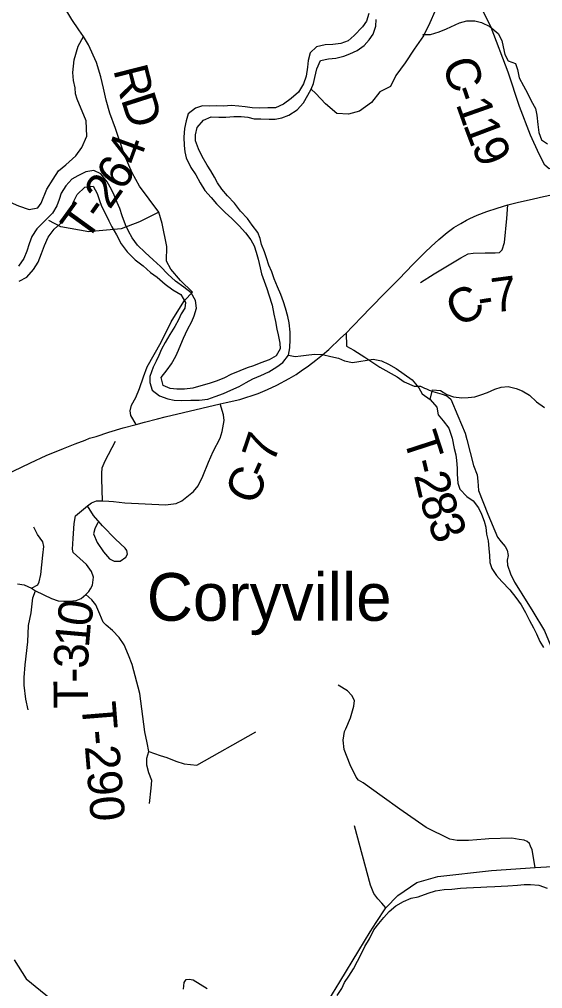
# Model space of a CAD drawing. Extents: x 0 to 34, y 0 to 22.
# Drawn here: x 3.344 to 4.209, y 15.794 to 17.398 of the extents above; entities that cross this region are included whole.
import ezdxf

# ---------------------------------------------------------------- set-up
doc = ezdxf.new("R2010")
doc.units = 0
for name, color, linetype in [('GM_X_City_Street', 7, 'Continuous'), ('GM_X_County_Road', 7, 'Continuous'), ('GM_X_County_Road_Text', 7, 'Continuous'), ('GM_X_Major_River', 7, 'Continuous'), ('GM_X_Minor_River', 7, 'Continuous'), ('GM_X_State_Route', 7, 'Continuous'), ('GM_X_Township_Road', 7, 'Continuous'), ('GM_X_Township_Road_Text', 7, 'Continuous'), ('GM_X_Unincorporated_Text', 7, 'Continuous')]:
    doc.layers.add(name, color=color, linetype=linetype)

msp = doc.modelspace()

# ---------------------------------------------------------------- linework, layer by layer
at = {"layer": 'GM_X_City_Street'}
for points in [[(3.3351, 15.8422), (3.355, 15.8107), (3.4028, 15.7721)], [(3.6151, 15.7933), (3.6163, 15.8047), (3.6197, 15.8093), (3.6246, 15.81), (3.6311, 15.8088), (3.6545, 15.7947)]]:
    msp.add_lwpolyline(points, dxfattribs=at)
at = {"layer": 'GM_X_County_Road'}
for points in [[(3.5371, 16.7279), (3.5284, 16.7427), (3.5273, 16.7507), (3.5295, 16.7598), (3.5364, 16.7725), (3.5425, 16.7873), (3.5494, 16.8066), (3.555, 16.8235), (3.5785, 16.8642), (3.595, 16.8979), (3.6074, 16.9184), (3.6169, 16.9333), (3.6305, 16.9469), (3.6106, 16.9661), (3.5945, 16.9852), (3.5873, 16.9983), (3.5879, 17.0227), (3.5802, 17.0607), (3.5744, 17.0795), (3.5427, 17.1224), (3.5305, 17.1447), (3.5177, 17.174), (3.503, 17.2177), (3.4935, 17.2431), (3.4877, 17.2645), (3.483, 17.2848), (3.4786, 17.3036), (3.4713, 17.3273), (3.4585, 17.3566), (3.4498, 17.3701), (3.4422, 17.3814), (3.4305, 17.3981), (3.419, 17.4174)], [(4.2627, 17.1168), (4.257, 17.1291), (4.2524, 17.1378), (4.2427, 17.15), (4.2346, 17.1567), (4.2201, 17.1513), (4.2127, 17.1571), (4.2036, 17.1755), (4.1895, 17.207), (4.1712, 17.2541), (4.1524, 17.3111), (4.1244, 17.385), (4.1095, 17.4154)], [(4.1518, 17.0918), (4.1671, 17.0954), (4.194, 17.1014), (4.211, 17.1054), (4.2342, 17.1105), (4.2627, 17.1168)], [(4.0072, 16.9628), (4.0299, 16.9772), (4.0741, 17.0039), (4.086, 17.0102), (4.0943, 17.0115), (4.1141, 17.0122), (4.1307, 17.0119), (4.1379, 17.0128), (4.1422, 17.0173), (4.1462, 17.029), (4.1501, 17.0688), (4.1518, 17.0918)], [(3.3411, 16.4643), (3.3518, 16.4626), (3.3642, 16.4572), (3.3704, 16.4526), (3.3973, 16.4398), (3.4079, 16.4359), (3.4172, 16.4356), (3.4268, 16.4356), (3.4377, 16.4366), (3.4463, 16.4401), (3.454, 16.4468), (3.4588, 16.4518), (3.4614, 16.4561), (3.4649, 16.4622), (3.4667, 16.4752), (3.4633, 16.4848), (3.455, 16.4965), (3.4327, 16.5162), (3.4316, 16.5216), (3.4329, 16.5391), (3.4345, 16.5642), (3.437, 16.5767), (3.4566, 16.5935), (3.4631, 16.5981), (3.4715, 16.6017), (3.4813, 16.6017), (3.4921, 16.6013), (3.4994, 16.6006), (3.5186, 16.5981), (3.5856, 16.5952), (3.6034, 16.597), (3.6128, 16.6014), (3.6317, 16.6169), (3.6396, 16.6267), (3.6476, 16.6423), (3.6567, 16.6655), (3.6643, 16.6833), (3.6762, 16.7054), (3.6795, 16.7163), (3.6824, 16.7348), (3.6813, 16.7438), (3.6762, 16.762)], [(3.4813, 16.6017), (3.4802, 16.6383), (3.4805, 16.647), (3.4809, 16.6561), (3.4856, 16.6677), (3.503, 16.7003)]]:
    msp.add_lwpolyline(points, dxfattribs=at)
at = {"layer": 'GM_X_Major_River'}
for points in [[(3.922, 17.408), (3.9182, 17.3955), (3.9114, 17.386), (3.8978, 17.3716), (3.8876, 17.3632), (3.8755, 17.3587), (3.8626, 17.3571), (3.8498, 17.3564), (3.8354, 17.3533), (3.8248, 17.3431), (3.8218, 17.3302), (3.8203, 17.3192), (3.8184, 17.3047), (3.8138, 17.2918), (3.8055, 17.2778), (3.7934, 17.2675), (3.781, 17.2584), (3.7677, 17.252), (3.7549, 17.2523), (3.7416, 17.2516), (3.7292, 17.2523), (3.7171, 17.2538), (3.7069, 17.255), (3.694, 17.2557), (3.6819, 17.255), (3.6698, 17.2553), (3.6577, 17.2546), (3.6468, 17.2553), (3.635, 17.2515), (3.6233, 17.242), (3.6195, 17.2303), (3.6169, 17.2181), (3.6158, 17.2037), (3.6165, 17.1897), (3.6173, 17.179), (3.6195, 17.1692), (3.6275, 17.1536), (3.6358, 17.1411), (3.643, 17.1282), (3.6509, 17.1153), (3.6611, 17.1036), (3.6698, 17.0933), (3.6845, 17.0789), (3.6955, 17.069), (3.7076, 17.0569), (3.7178, 17.0451), (3.7265, 17.0334), (3.7321, 17.0235), (3.7356, 17.0133), (3.739, 17.0015), (3.7423, 16.9871), (3.7442, 16.9776), (3.7488, 16.9651), (3.7533, 16.953), (3.7567, 16.9427), (3.762, 16.9253), (3.765, 16.9108), (3.7673, 16.8983), (3.7699, 16.8858), (3.7722, 16.8763), (3.7748, 16.8627), (3.7752, 16.8532), (3.7688, 16.8414), (3.7571, 16.835), (3.7435, 16.83), (3.731, 16.8251)], [(3.7189, 16.7974), (3.7298, 16.8035), (3.7435, 16.8088), (3.7567, 16.8152), (3.7699, 16.8236), (3.7797, 16.8308), (3.7888, 16.8429), (3.7911, 16.8551), (3.7915, 16.8684), (3.7919, 16.8809), (3.7903, 16.8964), (3.7881, 16.9067), (3.7843, 16.9203), (3.7805, 16.931), (3.7764, 16.9431), (3.7707, 16.956), (3.7654, 16.9689), (3.7616, 16.9807), (3.7567, 16.9917), (3.7526, 17.0038), (3.7492, 17.014), (3.7446, 17.0258), (3.742, 17.0357), (3.7382, 17.0455), (3.7291, 17.058), (3.7212, 17.0687), (3.7095, 17.0812), (3.6997, 17.0945), (3.6883, 17.1062), (3.6789, 17.1172), (3.6717, 17.1278), (3.6664, 17.1373), (3.6603, 17.1479), (3.6547, 17.1574), (3.646, 17.1715), (3.6399, 17.184), (3.6354, 17.1977), (3.635, 17.2075), (3.6377, 17.2197), (3.6486, 17.2318), (3.6611, 17.2371), (3.6736, 17.2364), (3.6853, 17.2364), (3.6985, 17.2379), (3.711, 17.2379), (3.722, 17.2364), (3.7322, 17.2341), (3.7435, 17.2337), (3.7571, 17.2334), (3.767, 17.2334), (3.7779, 17.2353), (3.7893, 17.2398), (3.8033, 17.249), (3.8138, 17.2603), (3.821, 17.2729), (3.8263, 17.2827), (3.8301, 17.2926), (3.8327, 17.3025), (3.8358, 17.3165), (3.8422, 17.3306), (3.8551, 17.3332), (3.8675, 17.3344), (3.8808, 17.3374), (3.8906, 17.3416), (3.9027, 17.3469), (3.9144, 17.3553), (3.9227, 17.3648), (3.9292, 17.3742), (3.9337, 17.3872), (3.9341, 17.3985)], [(3.731, 16.8251), (3.7204, 16.8217), (3.7083, 16.8167), (3.6939, 16.8107), (3.683, 16.8053), (3.6713, 16.8004), (3.658, 16.7958), (3.644, 16.7917), (3.6308, 16.7879), (3.6172, 16.7867), (3.6043, 16.7867), (3.5934, 16.7878), (3.5817, 16.7924), (3.5786, 16.8057), (3.5885, 16.8186), (3.5953, 16.8284), (3.6025, 16.841), (3.607, 16.8508), (3.6112, 16.8603), (3.6153, 16.8709), (3.6221, 16.885), (3.6293, 16.8983), (3.6331, 16.9078), (3.6369, 16.9203), (3.635, 16.9332), (3.6282, 16.9461), (3.6157, 16.9552), (3.6021, 16.9654), (3.5896, 16.9768), (3.5772, 16.9893), (3.5654, 17.0003), (3.5522, 17.0124), (3.5394, 17.025), (3.5303, 17.0371), (3.5242, 17.0481), (3.5197, 17.0583), (3.514, 17.0731), (3.5099, 17.0857), (3.5054, 17.0955), (3.5008, 17.1073), (3.4963, 17.1171), (3.4891, 17.1297), (3.4789, 17.1426), (3.4668, 17.1482), (3.4536, 17.146), (3.4407, 17.1395), (3.4309, 17.1338), (3.4207, 17.1232), (3.4131, 17.1107), (3.4097, 17.1004), (3.4059, 17.0898), (3.3988, 17.0776), (3.373, 17.0518), (3.3643, 17.0389), (3.3602, 17.0268), (3.3564, 17.015), (3.3511, 17.0025), (3.3424, 16.9903)], [(3.3435, 16.9653), (3.356, 16.9718), (3.3674, 16.9843), (3.3749, 16.9968), (3.3806, 17.0108), (3.3855, 17.0241), (3.3916, 17.0382), (3.4014, 17.0511), (3.412, 17.0606), (3.4233, 17.0731), (3.4301, 17.086), (3.4328, 17.0955), (3.4396, 17.1084), (3.4521, 17.1205), (3.4657, 17.1224), (3.4725, 17.1103), (3.4766, 17.0989), (3.48, 17.0891), (3.4861, 17.0765), (3.4917, 17.0652), (3.497, 17.0549), (3.5046, 17.042), (3.5125, 17.0272), (3.522, 17.0139), (3.5356, 17.0003), (3.5484, 16.9908), (3.5609, 16.9794), (3.5719, 16.9718), (3.5851, 16.9605), (3.5979, 16.951), (3.6112, 16.9434), (3.6187, 16.9301), (3.6176, 16.9206), (3.6115, 16.9112), (3.607, 16.9013), (3.601, 16.8899), (3.593, 16.877), (3.5851, 16.8637), (3.579, 16.8527), (3.5745, 16.8421), (3.5703, 16.8326), (3.565, 16.8227), (3.5597, 16.8072), (3.5597, 16.7977), (3.5635, 16.7848), (3.5756, 16.7753), (3.5896, 16.7704), (3.6002, 16.7685), (3.6127, 16.7678), (3.6274, 16.7681), (3.6414, 16.7685), (3.6554, 16.77), (3.6678, 16.7742), (3.6815, 16.7792), (3.6939, 16.7849), (3.7072, 16.7909), (3.7189, 16.7974)]]:
    msp.add_lwpolyline(points, dxfattribs=at)
at = {"layer": 'GM_X_Minor_River'}
for points in [[(4.0992, 17.5016), (4.0829, 17.4803), (4.0753, 17.4632), (4.0612, 17.4453), (4.0487, 17.4282), (4.0309, 17.4114), (4.0225, 17.3928), (4.0122, 17.3715), (3.9967, 17.3494), (3.9822, 17.3266), (3.9667, 17.3057), (3.9575, 17.2875), (3.9401, 17.2783), (3.9261, 17.2609), (3.9067, 17.2464), (3.8885, 17.2415), (3.8689, 17.2427), (3.85, 17.2587), (3.8341, 17.2758), (3.8263, 17.2827)], [(4.0122, 17.3715), (4.0116, 17.3735), (4.0237, 17.3735), (4.0384, 17.3781), (4.0501, 17.3827), (4.072, 17.3925), (4.0838, 17.3963), (4.097, 17.3963), (4.108, 17.3933), (4.1219, 17.3865), (4.1355, 17.3751), (4.1416, 17.3633), (4.1439, 17.3531), (4.1469, 17.3402), (4.1525, 17.3299), (4.1643, 17.3254), (4.168, 17.3155), (4.1703, 17.3019), (4.1779, 17.2886), (4.1843, 17.2764), (4.1903, 17.2639), (4.1975, 17.251), (4.1998, 17.24), (4.2013, 17.2244), (4.2028, 17.2112), (4.2073, 17.199), (4.2172, 17.1926)], [(3.7888, 16.8429), (3.7998, 16.8407), (3.8096, 16.8418), (3.8228, 16.8433), (3.8327, 16.8445), (3.8455, 16.8441), (3.8588, 16.8403), (3.8716, 16.8377), (3.8814, 16.8335), (3.8947, 16.8308), (3.9056, 16.8324), (3.9189, 16.8346), (3.9291, 16.8362), (3.9427, 16.8335), (3.9544, 16.8278), (3.9669, 16.8206), (3.9805, 16.8111), (3.9933, 16.802), (4.0043, 16.7884), (4.0099, 16.7789), (4.0232, 16.7691), (4.0341, 16.7569), (4.0368, 16.744), (4.0447, 16.7338), (4.0542, 16.722), (4.0598, 16.7053), (4.0632, 16.6883), (4.0655, 16.678), (4.0666, 16.6682), (4.0678, 16.6556), (4.0681, 16.6458), (4.0689, 16.6306), (4.0723, 16.6208), (4.084, 16.6086), (4.0946, 16.6014), (4.1033, 16.59), (4.1082, 16.5794), (4.1127, 16.568), (4.1154, 16.5578), (4.1165, 16.5464), (4.1191, 16.5354), (4.1206, 16.5225), (4.1214, 16.5112), (4.1222, 16.4994), (4.1252, 16.4895), (4.1331, 16.4778), (4.1418, 16.4679), (4.155, 16.4543), (4.1652, 16.4414), (4.1736, 16.4296), (4.1807, 16.4167), (4.1875, 16.4035), (4.194, 16.3917), (4.1992, 16.3815), (4.2049, 16.3686), (4.2106, 16.3591)], [(3.7888, 16.8429), (3.7888, 16.8433)], [(4.0232, 16.7691), (4.0273, 16.7854), (4.0402, 16.7842), (4.0511, 16.7774), (4.0621, 16.774), (4.0757, 16.7721), (4.0859, 16.7725), (4.0973, 16.774), (4.1071, 16.7771), (4.1184, 16.7812), (4.1301, 16.7866), (4.1407, 16.7896), (4.1521, 16.7907), (4.1657, 16.7873), (4.1755, 16.7835), (4.1876, 16.7763), (4.1993, 16.7653), (4.2122, 16.7562)], [(3.8695, 15.7829), (3.8774, 15.7946), (3.8816, 15.8045), (3.8888, 15.8147), (3.8967, 15.8269), (3.9032, 15.8398), (3.9096, 15.8523), (3.9153, 15.8641), (3.9232, 15.8766), (3.93, 15.8914), (3.9383, 15.902), (3.9466, 15.9122), (3.9553, 15.9217), (3.9663, 15.9316), (3.9792, 15.9384), (3.992, 15.9441), (4.0034, 15.9464), (4.02, 15.9525), (4.0321, 15.9563), (4.0464, 15.9582), (4.0589, 15.9589), (4.0737, 15.9604), (4.0835, 15.9612), (4.0952, 15.9616), (4.1069, 15.9624), (4.1168, 15.9627), (4.13, 15.9635), (4.1406, 15.9639), (4.1519, 15.9647), (4.1678, 15.9658), (4.1787, 15.9669), (4.1893, 15.9669), (4.2029, 15.9654), (4.2169, 15.9605)]]:
    msp.add_lwpolyline(points, dxfattribs=at)
at = {"layer": 'GM_X_State_Route'}
for p, q in [((3.6762, 16.762), (3.686, 16.7643)), ((3.9342, 15.9036), (3.9501, 15.9279))]:
    msp.add_line(p, q, dxfattribs=at)
for points in [[(4.1518, 17.0918), (4.1671, 17.0954), (4.194, 17.1014), (4.211, 17.1054), (4.2342, 17.1105), (4.2627, 17.1168)], [(3.686, 16.7643), (3.7085, 16.7696), (3.7386, 16.7794), (3.7542, 16.7858), (3.7698, 16.7933), (3.7899, 16.8041), (3.8016, 16.811), (3.81, 16.8166), (3.8221, 16.8249), (3.8343, 16.8342), (3.8455, 16.8431), (3.8557, 16.852), (3.875, 16.8707), (3.8843, 16.8792), (3.8949, 16.8904), (3.9118, 16.9078), (3.923, 16.9193), (3.9507, 16.9477), (3.9719, 16.9693), (3.9948, 16.9927), (4.0029, 17.0011), (4.0148, 17.0131), (4.0247, 17.0226), (4.0378, 17.0344), (4.0517, 17.0456), (4.0625, 17.0538), (4.0738, 17.0608), (4.0834, 17.0661), (4.089, 17.0689), (4.1011, 17.0743), (4.117, 17.0807), (4.1341, 17.0862), (4.1518, 17.0918)], [(3.5371, 16.7279), (3.5508, 16.7321), (3.5726, 16.7373), (3.5853, 16.7406), (3.6762, 16.762)], [(3.102, 16.494), (3.1088, 16.5002), (3.1391, 16.5253), (3.158, 16.5407), (3.1695, 16.5496), (3.2033, 16.5739), (3.224, 16.5878), (3.2682, 16.6153), (3.2999, 16.6333), (3.3345, 16.6514), (3.3611, 16.6641), (3.3624, 16.6646), (3.3885, 16.6767), (3.4167, 16.6883), (3.4364, 16.6961), (3.4525, 16.702), (3.4601, 16.7051), (3.4709, 16.7083), (3.4917, 16.7154), (3.5156, 16.7225), (3.5371, 16.7279)], [(3.9501, 15.9279), (3.9698, 15.9484), (4.0012, 15.9699), (4.0362, 15.9799), (4.1249, 15.9899), (4.1968, 15.9947), (4.2431, 15.9978)], [(3.6204, 15.4648), (3.622, 15.466), (3.6381, 15.4802), (3.6679, 15.519), (3.681, 15.5402), (3.6917, 15.5618), (3.7094, 15.6057), (3.7367, 15.6553), (3.7625, 15.6833), (3.8051, 15.7156), (3.8178, 15.7276), (3.8374, 15.7462), (3.8739, 15.8055), (3.9055, 15.8575), (3.9241, 15.8881), (3.9342, 15.9036)]]:
    msp.add_lwpolyline(points, dxfattribs=at)
at = {"layer": 'GM_X_Township_Road'}
for points in [[(3.2918, 17.1124), (3.3044, 17.1065), (3.3425, 17.0897), (3.3603, 17.0839), (3.3743, 17.0863), (3.3801, 17.0941), (3.3895, 17.1174), (3.3998, 17.1342), (3.4089, 17.148), (3.4206, 17.1579), (3.4373, 17.1726), (3.4472, 17.1863), (3.4553, 17.2051), (3.4545, 17.2306), (3.4393, 17.2664), (3.4369, 17.2752), (3.4364, 17.2854), (3.4333, 17.2973), (3.4326, 17.3106), (3.4347, 17.3315), (3.441, 17.3544), (3.4498, 17.3701)], [(3.5744, 17.0795), (3.5426, 17.0636), (3.5122, 17.0516), (3.4639, 17.0472)], [(3.4639, 17.0472), (3.4587, 17.0468), (3.4124, 17.055), (3.3929, 17.0656)], [(3.8843, 16.8792), (3.8848, 16.8575), (3.8972, 16.8508), (3.9151, 16.8394), (3.9402, 16.823), (3.9686, 16.8068), (3.9802, 16.7986), (3.9971, 16.7914), (4.0073, 16.7912), (4.0141, 16.7881)], [(4.0141, 16.7881), (4.0171, 16.7868), (4.0215, 16.785), (4.0276, 16.7824), (4.043, 16.7783), (4.0509, 16.7754), (4.0573, 16.77), (4.0688, 16.7424), (4.081, 16.7137), (4.0842, 16.703), (4.095, 16.6602), (4.1008, 16.6445), (4.1024, 16.6342), (4.1032, 16.619), (4.1187, 16.5796), (4.1349, 16.5417), (4.1408, 16.5336), (4.1471, 16.5258), (4.1507, 16.5201), (4.1524, 16.5113), (4.1508, 16.5037), (4.1513, 16.495), (4.1559, 16.4809), (4.1628, 16.467), (4.172, 16.4522)], [(3.4736, 16.5658), (3.4687, 16.5555), (3.4664, 16.5471), (3.4725, 16.5326), (3.4828, 16.5173), (3.4931, 16.5054), (3.5008, 16.5016), (3.5107, 16.502), (3.5202, 16.5085), (3.5229, 16.5131), (3.5218, 16.5192), (3.5191, 16.5234), (3.503, 16.5383), (3.4816, 16.5605), (3.4667, 16.5773), (3.4566, 16.5935)], [(3.3642, 16.4572), (3.3743, 16.4628), (3.3768, 16.4675), (3.3792, 16.4795), (3.3826, 16.5119), (3.3845, 16.526), (3.3826, 16.5339), (3.3741, 16.5459), (3.3681, 16.5579)], [(3.3583, 16.256), (3.3548, 16.2736), (3.3519, 16.2967), (3.3519, 16.3094), (3.3535, 16.3304), (3.3579, 16.3684), (3.3591, 16.3951), (3.3633, 16.4164), (3.3662, 16.4412), (3.3704, 16.4526)], [(3.559, 16.1007), (3.5619, 16.1263), (3.5631, 16.1387), (3.5578, 16.1514), (3.5547, 16.1643), (3.5549, 16.1755), (3.5583, 16.1865), (3.5554, 16.2011), (3.5513, 16.2195), (3.5479, 16.2447), (3.543, 16.283), (3.5306, 16.3306), (3.5245, 16.3463), (3.5172, 16.3632), (3.5088, 16.3755), (3.498, 16.3868), (3.4873, 16.3956), (3.4826, 16.401), (3.477, 16.4142), (3.4702, 16.4295), (3.4638, 16.4377), (3.454, 16.4468)], [(4.172, 16.4522), (4.1747, 16.4478), (4.1929, 16.4186), (4.2126, 16.3863), (4.2256, 16.3545), (4.2435, 16.3271), (4.2652, 16.2933), (4.2848, 16.2716), (4.3019, 16.2553), (4.3158, 16.2349), (4.3204, 16.2207), (4.3172, 16.209), (4.3177, 16.2003), (4.3243, 16.1909)], [(3.8836, 16.2243), (3.8916, 16.2423), (3.8973, 16.2616), (3.8979, 16.2714), (3.8939, 16.2795), (3.8868, 16.2872), (3.8711, 16.2963)], [(3.5583, 16.1865), (3.5769, 16.18), (3.5877, 16.1767), (3.6025, 16.1707), (3.6166, 16.1664), (3.6374, 16.164), (3.7351, 16.2192)], [(3.9731, 16.0915), (3.9437, 16.1121), (3.9127, 16.1348), (3.9049, 16.1392), (3.9008, 16.1442), (3.891, 16.1645), (3.8809, 16.1898), (3.8794, 16.2054), (3.8816, 16.2198), (3.8836, 16.2243)], [(4.114, 16.0418), (4.0865, 16.0397), (4.0679, 16.0397), (4.0558, 16.0418), (4.0168, 16.0609), (3.9731, 16.0915)], [(3.9501, 15.9279), (3.9433, 15.936), (3.9366, 15.943), (3.9303, 15.9515), (3.9246, 15.9656), (3.8983, 16.0638)], [(4.1968, 15.9947), (4.1919, 16.0238), (4.1893, 16.0299), (4.1875, 16.0345), (4.1838, 16.038), (4.1786, 16.04), (4.1703, 16.0413), (4.1582, 16.0431), (4.1206, 16.0424), (4.114, 16.0418)]]:
    msp.add_lwpolyline(points, dxfattribs=at)

# ---------------------------------------------------------------- texts
at = {"layer": 'GM_X_County_Road_Text'}
for s, rotation, p in [('C', 289.1308, (4.0422, 17.325)), ('R', 284.28, (3.4989, 17.3152)), ('D', 287.8984, (3.5114, 17.2662)), ('-', 289.1996, (4.0575, 17.2808)), ('1', 289.4769, (4.0653, 17.2585)), ('1', 290.6915, (4.0774, 17.2243)), ('9', 293.1822, (4.0908, 17.189)), ('7', 7.6175, (4.1284, 16.913)), ('C', 30.7029, (4.0709, 16.8874)), ('-', 9.1916, (4.1058, 16.9094)), ('7', 71.2453, (3.7644, 16.6616)), ('C', 65.4125, (3.7332, 16.592)), ('-', 66.0063, (3.7529, 16.635))]:
    msp.add_text(s, height=0.0568, rotation=rotation, dxfattribs=at).set_placement(p)
at = {"layer": 'GM_X_Township_Road_Text'}
for s, height, rotation, p in [('4', 0.0568, 69.9056, (3.5405, 17.1546)), ('6', 0.0568, 56.4359, (3.5146, 17.1125)), ('2', 0.0568, 54.6929, (3.4933, 17.0823)), ('T', 0.0568, 54.1188, (3.4544, 17.0285)), ('-', 0.0568, 54.228, (3.4794, 17.063)), ('T', 0.0568, 287.9894, (3.9781, 16.7059)), ('-', 0.0568, 283.127, (3.9909, 16.6667)), ('2', 0.0568, 283.023, (3.9962, 16.644)), ('8', 0.0568, 287.3483, (4.0053, 16.6053)), ('3', 0.0568, 292.8918, (4.0178, 16.5663)), ('0', 0.0568, 81.5862, (3.4617, 16.3914)), ('1', 0.0568, 84.8776, (3.4587, 16.3574)), ('3', 0.0568, 87.7096, (3.4573, 16.3232)), ('-', 0.0568, 89.6643, (3.4572, 16.3004)), ('T', 0.0568, 90.3514, (3.4574, 16.258)), ('T-290', 0.05682, 274.6514, (3.4464, 16.267))]:
    msp.add_text(s, height=height, rotation=rotation, dxfattribs=at).set_placement(p)
at = {"layer": 'GM_X_Unincorporated_Text'}
msp.add_text('Coryville', height=0.07898, rotation=0, dxfattribs=at).set_placement((3.5547, 16.4031))

doc.saveas('drawing.dxf')
